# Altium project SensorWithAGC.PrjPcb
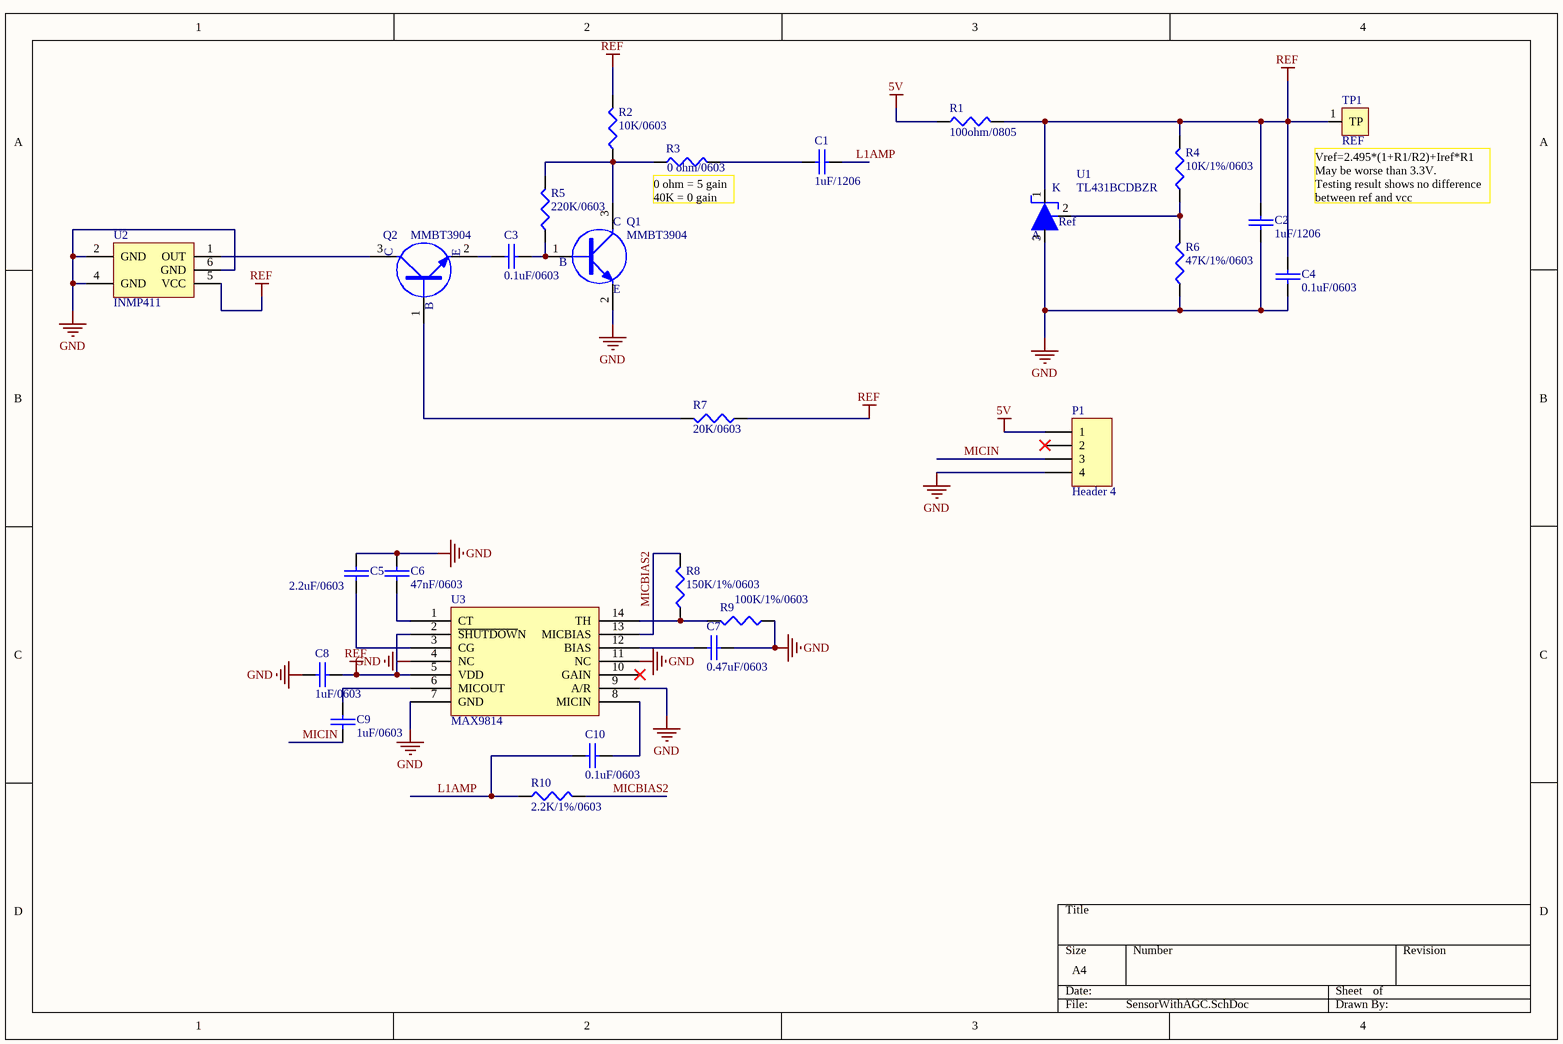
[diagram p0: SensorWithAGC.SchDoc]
1 sheet, 27 parts. Net scope: global (net labels, ports and power ports of the same name join across sheets).
Board file: SensorWithAGC.PcbDoc

## Sheet SensorWithAGC.SchDoc
size A4

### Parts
C1  1uF/1206  [TAN_A]
C2  1uF/1206  [TAN_A]
C3  0.1uF/0603  [C0603]
C4  0.1uF/0603  [C0603]
C5  2.2uF/0603  [C0603]
C6  47nF/0603  [C0603]
C7  0.47uF/0603  [C0603]
C8  1uF/0603  [C0603]
C9  1uF/0603  [C0603]
C10  0.1uF/0603  [C0603]
P1  Header 4  [HDR1X4]
Q1  MMBT3904  [SOT-23]
Q2  MMBT3904  [SOT-23]
R1  100ohm/0805  [R0603]
R2  10K/0603  [R0603]
R3  0 ohm/0603  [R0603]
R4  10K/1%/0603  [R0603]
R5  220K/0603  [R0603]
R6  47K/1%/0603  [R0603]
R7  20K/0603  [R0603]
R8  150K/1%/0603  [R0603]
R9  100K/1%/0603  [R0603]
R10  2.2K/1%/0603  [R0603]
TP1  REF  [TP]
U1  TL431BCDBZR  [SOT-23]
U2  INMP411  [INMP411]
U3  MAX9814  [DFN300X300X80-15N]

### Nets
5V: P1.1 R1.1
GND: C2.2 C4.2 C5.2 C6.2 C7.2 C8.2 P1.4 Q1.2(E) R6.1 R9.1 U1.3(A) U2.2(GND) U2.4(GND) U2.6(GND) U3.4(NC) U3.7(GND) U3.9(A/R) U3.11(NC)
REF: C2.1 C4.1 C8.1 R1.2 R2.2 R4.2 R7.1 TP1.1(TP) U1.1(K) U2.5(VCC) U3.2(~{SHUTDOW}N) U3.5(VDD)
L1AMP: C1.1 C10.1 R10.1
MICBIAS2: R8.2 R10.2 U3.13(MICBIAS)
MICIN: C9.2 P1.3
NetC1_2: C1.2 R3.2
NetC3_1: C3.1 Q1.1(B) R5.1
NetC3_2: C3.2 Q2.2(E)
NetC5_1: C5.1 U3.3(CG)
NetC6_1: C6.1 U3.1(CT)
NetC7_1: C7.1 U3.12(BIAS)
NetC9_1: C9.1 U3.6(MICOUT)
NetC10_2: C10.2 U3.8(MICIN)
NetQ1_3: Q1.3(C) R2.1 R3.1 R5.2
NetQ2_1: Q2.1(B) R7.2
NetQ2_3: Q2.3(C) U2.1(OUT)
NetR4_1: R4.1 R6.2 U1.2(REF)
NetR8_1: R8.1 R9.2 U3.14(TH)

Not connected (* = marked no-connect by the designer): P1 2*; U3 10(GAIN)*

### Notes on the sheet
- (near R3) 0 ohm = 5 gain
  40K = 0 gain
- (near TP1) Vref=2.495*(1+R1/R2)+Iref*R1
  May be worse than 3.3V.
  Testing result shows no difference
  between ref and vcc

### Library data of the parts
C1-C10 = C
P1 = Header 4: Header, 4-Pin
Q1 Q2 = MMBT3904: NPN Transistor
R1-R10 = RES
TP1 = Testpoint
U1 = TL431CDBZR: CAN NOT BE MFDT or MSDT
